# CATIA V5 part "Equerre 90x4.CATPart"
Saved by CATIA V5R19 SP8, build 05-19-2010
Part number: Equerre 90x4
Nomenclature: MAKER100304
Bounding box of the stored display mesh (mm): x 0 to 1.5, y -15 to 5, z -5 to 25
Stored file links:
  D:\Documents\1_Travail\1 - ac-limoges.fr\ac-limoges.fr\Emmanuel Maynard - STI2D_Turgot\1 - IT-I2D\Activités_IT_Première\IT_3_Abris_bus\Maquettes numériques\Abribus_eleve\Equerre 90x4.CATPart
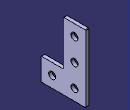
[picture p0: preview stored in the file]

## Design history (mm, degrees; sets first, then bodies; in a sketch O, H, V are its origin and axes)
AxisSystem1: origin (0, 0, 0), X (1, 0, 0), Y (0, 1, 0), Z (0, 0, 1)
Body1 (main body)
  Sketch1 on YZ plane of AxisSystem1, origin (0, 0, 0), H (0, 1, 0), V (0, 0, 1)
    line L1 (-15, -5) -> (5, -5)
    line L2 (5, -5) -> (5, 25)
    line L3 (5, 25) -> (-5, 25)
    line L4 (-5, 25) -> (-5, 5)
    line L5 (-5, 5) -> (-15, 5)
    line L6 (-15, 5) -> (-15, -5)
    distance L4 L2 = 10
    distance L4 V = 5
    distance L1 H = 5
    distance L5 L1 = 10
    distance L6 L2 = 20
    distance L3 L1 = 30
    horizontal: L1 H, L3 H, L5 H
    vertical: L2 V, L4 V, L6 V
  Pad1: profile Sketch1, direction (1, 0, 0), length 1.5
  Fillet1: radius 0.2, on edge [face of Pad1 from Sketch1.L2 | face of Pad1 from Sketch1.L1]; edge [face of Pad1 from Sketch1.L1 | face of Pad1 from Sketch1.L6]; edge [face of Pad1 from Sketch1.L6 | face of Pad1 from Sketch1.L5]; edge [face of Pad1 from Sketch1.L5 | face of Pad1 from Sketch1.L4]; edge [face of Pad1 from Sketch1.L4 | face of Pad1 from Sketch1.L3]; edge [face of Pad1 from Sketch1.L3 | face of Pad1 from Sketch1.L2]
  Sketch2 on end face of Pad1, origin (1.5, 0, 0), H (0, 1, 0), V (0, 0, 1)
    circle A1 centre (0, 0) radius 1.55
    radius A1 = 1.55
  Pocket1: profile Sketch2, direction (-1, 0, 0), length 1.5
  RectPattern1: of Pocket1, direction 1 instances 3, spacing 10, along edge [face of Pad1 from Sketch1.L2 | end face of Pad1], direction 2 instances 2, spacing 10, along edge [face of Pad1 from Sketch1.L1 | end face of Pad1] reversed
